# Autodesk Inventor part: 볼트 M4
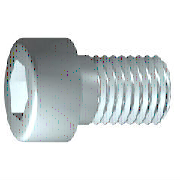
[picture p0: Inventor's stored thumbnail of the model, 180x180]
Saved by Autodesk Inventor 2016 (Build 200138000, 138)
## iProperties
IsCustomPart: 1
Created: 2012-02
Part Number: 볼트 M4
Material: 강철, 연강
Description: 6각머리 태핑 나사
Document SubType Name: Modeling
Standard: KS B 1003
Designer: test
Standards Organization: KS
Language: ko-KR
Size Designation: M 4 x 10
Categories: <MemberInstance><Categories><Category DisplayName="조임쇠" InternalName="e4da775c-781d-43d5-af7c-5136215cf5a6" Mnemonic="FSTN"><Category DisplayName="볼트" InternalN
Density: 1 g/cm^3
Appearance: 강철
Author: test
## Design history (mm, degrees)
sketch "스케치1"
  geometry: L1 (-1, 0)-(10, 0); L2 (10, 0)-(10, 2); L3 (10, 2)-(1.75, 2); L4 (1.75, 2)-(1.32, 2); L5 (1.32, 2)-(0, 2); L6 (0, 2)-(0, 3.5); L7 (0, 3.5)-(-4, 3.5); L8 (-4, 3.5)-(-4, 1.732); L9 (-4, 1.732)-(-2, 1.732); L10 (-2, 1.732)-(-1, 0); L11 (-6.8, 0)-(12.8, 0) reference; L12 (0, -0.7)-(0, 4.2) reference; L13 (1.75, 2)-(0, 2)
  constraints: 22 end point, 6 parallel, 2 collinear, 2 perpendicular, 1 horizontal, 1 point on line
  dimensions: "d1" = 8.25 distance from line of L3.end L2 (= GEL); "d2" = 0.42952 distance of L4.end L3.end (computed from GAL); "d3" = 4 distance between parallel lines of L8 L6 (= KOH); "d4" = 2 distance of L8.end L9.end (= INTI); "d5" = 60 deg angle of L10 L1; "d6" = 4 diameter of L3 L1 (= GD); "d7" = 4 diameter of L5 L1 (= BDM); "d8" = 3.4641 diameter of L9 L1 (= 1.1547 x SW); "d9" = 7 diameter of L7 L1 (= KOD); "d26" = 10 distance between parallel lines of L12 L2 (= NLG)
revolve "본체" sketch "스케치1" stored, may be unused: angle "d10" = 90 deg
sketch "스케치2"
  geometry: L1 (0, -4.9)-(0, 4.9) reference; L2 (-4.9, 0)-(4.9, 0) reference; L3 (1.732, 0)-(0.866, -1.5); L4 (0.866, -1.5)-(-0.866, -1.5); L5 (-0.866, -1.5)-(-1.732, 0); L6 (-1.732, 0)-(-0.866, 1.5); L7 (-0.866, 1.5)-(0.866, 1.5); L8 (0.866, 1.5)-(1.732, 0); 2 further points
  constraints: 12 end point, 1 coincident, 1 horizontal alignment, 1 point on line, 12 other
extrude "슬롯" join sketch "스케치2" stored distance "d11" = 10; taper "d12" = 0 deg
workplane "Work Plane1"
fillet "Fillet2" dims "d30" = 0.1 (= R)
body "Solid1"
fillet "모깎기1" dims "d17" = 0.4 (= RR)
feature "스레드" dims "d13" = 8.25 (= GEL), "d14" = 0
chamfer "모따기1" distance "d15" = 0.42941 (= -0.5 x SPD + 0.5 x GD); stored, may be unused: second distance "d16" = 0.42941 (= GUL), angle "d27" = 45 deg
other parameters: "GD" = 4 (= NND) [user parameter; used in 2 equation terms], "NLG" = 10 [user parameter; used in 1 equation term], "GEL" = 8.25 [user parameter; used in 2 equation terms], "KOD" = 7 [user parameter; used in 1 equation term], "KOH" = 4 [user parameter; used in 1 equation term], "INTI" = 2 [user parameter; used in 1 equation term], "GAL" = 0.42941 (= 0.61345 x PTC) [user parameter; used in 1 equation term], "GUL" = 0.42941 (= 0.61345 x PTC) [user parameter; used in 1 equation term], "BDM" = 4 (= NND) [user parameter; used in 1 equation term], "SW" = 3 [user parameter; used in 2 equation terms], "RR" = 0.4 [user parameter; used in 1 equation term], "SPD" = 3.14117 (= NND - 1.2269 x PTC) [user parameter; used in 1 equation term], "d19" = 0, "d28" = 0, "d29" = 0, "R" = 0.1 [user parameter; used in 1 equation term], "PHH" = 0.2 [user parameter], "GD1" = 3.14117 (= THREADDIA - 1.2269 x PTC) [user parameter], "THREADDIA" = 4 [user parameter; used in 1 equation term], "FAWI" = 45 deg [user parameter], "TPU" = 14.28571 (computed from PTC) [user parameter], "PTC" = 0.7 [user parameter; used in 5 equation terms], "NND" = 4 [user parameter; used in 3 equation terms], "TOA" = 30 deg [user parameter], "E0" = 3.465 (= 1.155 x SW) [user parameter]
